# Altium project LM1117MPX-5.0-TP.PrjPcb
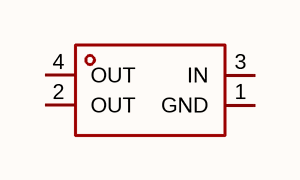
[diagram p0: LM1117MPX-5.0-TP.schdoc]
1 sheet, 1 parts. Net scope: global (net labels, ports and power ports of the same name join across sheets).

## Sheet LM1117MPX-5.0-TP.schdoc
size 127 x 101 mm

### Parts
U?  lm1117mpx-5.0-tp  [SOT-223-3_L6.4-W3.5-P2.30-LS7.0-BR]  (value not drawn)

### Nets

Not connected (* = marked no-connect by the designer): U? 1(GND) 2(OUT) 3(IN) 4(OUT)

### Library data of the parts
U? = lm1117mpx-5.0-tp: 输出极性:正极;工作电压:18V;输出电压:5V;输出电流:1A;输出类型:固定;; Manufacturer: TECH PUBLIC(台舟); AddInBom: yes; ModelId: 6654433eca7b4e7f8ee05e27058a22e4; ModelTransform: 251.968,275.59,0,90,0,0,-3.937,0,0; Output Configuration: 正极; Voltage - Supply: 18V; Output Voltage: 5V; Output Current: 1A; standby current: 4mA; Output Type: 固定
